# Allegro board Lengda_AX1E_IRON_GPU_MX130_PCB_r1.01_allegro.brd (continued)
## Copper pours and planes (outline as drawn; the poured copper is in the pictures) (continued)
GND on BOTTOM (solid shape): 43.49,52.23 44.48,52.23 44.58,52.14 44.58,47.16 44.44,47.03 44.44,47.02 44.37,46.95 44.37,45.12 44.3,45.05 44.3,42.58 44.29,42.58 43.28,42.58 43.26,42.6 43.26,43.36 43.61,43.71 43.61,43.72 43.8,43.91 43.8,44.47 43.7,44.57 43.41,44.57 43.28,44.7 43.26,44.72 43.26,45.03 43.36,45.13 43.4,45.13 43.53,45.26 43.53,46.34 43.46,46.41 43.21,46.41 43.19,46.44 43.19,47.06 43.36,47.23 43.36,48.42 43.16,48.62 43.16,49.13 42.92,49.37 42.47,49.37 42.08,49.76 42.08,50.24 42,50.31 41.41,50.31 41.16,50.07 41.16,49.76 41.1,49.7 40.24,49.7 40.18,49.75 40.18,52.1 40.24,52.15 42.21,52.15 42.4,52.35 43.37,52.35
GND on BOTTOM (solid shape): outline of 337 points within 31.01,32.84 38.96,52.39
GND on BOTTOM (solid shape): outline of 548 points within 7.01,3.51 76.19,97.79
GND on L2 (solid shape): outline of 35099 points within 7.01,0.41 76.19,97.79
GND on L3 (solid shape): outline of 531 points within 7.01,0.41 76.19,97.79
GND on L4 (solid shape): outline of 11258 points within 7.01,0.41 76.19,97.79
GND on L5 (solid shape): outline of 35099 points within 7.01,0.41 76.19,97.79
GND on L6 (solid shape): outline of 1050 points within 7.01,0.41 76.19,97.79
GND on L7 (solid shape): outline of 35079 points within 7.01,0.41 76.19,97.79
VDD_GPU on BOTTOM (solid shape): 66.54,64.28 66.54,63.82 66.74,63.62 66.74,62.2 66.61,62.07 65.82,62.07 65.43,61.68 62.52,61.68 62.27,61.92 62.27,64.32 62.45,64.5 66.32,64.5
VDD_GPU_AON on BOTTOM (solid shape): 65.75,60.78 66.61,60.78 66.71,60.67 66.71,60 66.36,59.64 65.15,59.64 64.9,59.39 64.9,57.22 64.19,56.51 64.19,53.9 63.7,53.42 61.91,53.42 61.84,53.5 61.84,54.22 61.29,54.77 61.29,57.13 61.62,57.46 62.1,57.46 62.7,58.06 62.7,59.67 62.43,59.94 62.43,60.84 62.6,61 65.52,61
VDD_GPU_MAIN on BOTTOM (solid shape): outline of 165 points within 55.74,53.42 61.09,58.57
+VSYS_DCIN on TOP (solid shape): outline of 100 points within 67.39,57.83 74.51,63.82
+VSYS_DCIN on TOP (solid shape): outline of 2921 points within 9.23,0.32 72.81,49.33
+VSYS_DCIN on BOTTOM (solid shape): outline of 148 points within 66.68,11.28 75.45,64.76
FB_PLLAVDD on BOTTOM (solid shape): 54.83,56.42 55.78,56.42 55.88,56.32 55.88,55.43 55.28,54.83 55.28,54.37 54.95,54.04 54.1,54.04 53.66,54.49 50.98,54.49 50.76,54.7 49.5,54.7 49.28,54.93 49.28,56.15 49.4,56.28 50.09,56.28 50.22,56.15 50.22,55.63 50.39,55.45 51.13,55.45 51.26,55.33 53.06,55.33 53.43,55.7 53.43,56.65 53.54,56.76 54.48,56.76
FB_PLLAVDD on L3 (solid shape): outline of 1169 points within 32.45,48.93 50.14,55.56
FBVDD on TOP (solid shape): 22.19,87.36 22.19,86.15 21.37,85.34 21.37,84.75 21.25,84.63 20.33,84.63 20.05,84.35 20.05,81.68 20.42,81.31 21.25,81.31 21.5,81.06 21.5,80.32 21.25,80.07 20.08,80.07 19.81,80.33 19.08,80.33 18.21,81.2 18.21,87.13 18.58,87.5 22.05,87.5
FBVDD on TOP (solid shape): 49.25,87.84 49.25,86.63 47.88,85.26 47.88,81.51 44.12,77.75 44.12,73.17 42.7,71.75 38.16,71.75 37.83,72.08 37.83,74.72 39.93,74.72 39.93,72.28 40,72.21 42.16,72.21 42.25,72.29 42.25,74.76 42.19,74.82 42.19,74.83 40.04,74.83 39.93,74.72 37.83,74.72 37.83,79.3 36.35,80.79 34.75,80.79 34.61,80.93 34.61,81.65 34.94,81.98 35.89,81.98 36.07,82.16 36.07,83.67 35.85,83.89 34.71,83.89 34.63,83.97 34.63,84.4 40.28,84.4 40.28,81.72 40.49,81.51 42.38,81.51 42.56,81.69 42.56,84.38 42.29,84.65 40.54,84.65 40.28,84.4 34.63,84.4 34.63,84.66 34.87,84.91 36.17,84.91 36.55,85.29 36.55,87.34 37.41,88.21 48.88,88.21
FBVDD on TOP (solid shape): outline of 324 points within 12.4,45.29 25.82,82.15
FBVDD on TOP (solid shape): outline of 194 points within 31.98,46.18 44.18,54.32
FBVDD on BOTTOM (solid shape): outline of 2837 points within 9.27,44.75 67.98,90.26
FBVDD on L4 (solid shape): outline of 19972 points within 12.7,44.66 65.21,87.2
GPU_PLLVDD on BOTTOM (solid shape): 60.91,61.77 60.91,59.59 60.4,59.09 58.89,59.09 58.69,59.29 58.69,60.32 58.33,60.67 57.12,60.67 56.96,60.84 56.96,61.75 57.18,61.97 60.71,61.97
GPU_PLLVDD on BOTTOM (solid shape): 40.28,36.53 40.28,34.49 39.87,34.07 38.53,34.07 38.42,34.18 38.42,35.82 38.42,36.42 38.59,36.59 40.23,36.59
NVVDD on TOP (solid shape): outline of 1458 points within 55.65,27.55 69.42,48.44
NVVDD on TOP (solid shape): outline of 1802 points within 32.95,25.88 46.74,52.42
NVVDD on BOTTOM (solid shape): 59.18,34.04 59.18,32.03 60.31,30.9 61.59,30.9 62.24,30.26 62.24,24.79 62.1,24.66 56.62,24.66 55.84,25.43 55.84,35.13 56.24,35.53 57.7,35.53
NVVDD on BOTTOM (solid shape): outline of 622 points within 35.1,24.91 46.33,51.93
NVVDD on L3 (solid shape): outline of 4621 points within 34.19,19.74 59.61,51.8
NVVDD on L4 (solid shape): outline of 4760 points within 34.3,19.75 59.55,51.67
NVVDD on L6 (solid shape): outline of 4985 points within 31.1,20.47 61.73,52.02
PEX_PLL_HVDD on BOTTOM (solid shape): 45.23,44.09 45.23,43.03 45.12,42.78 45.23,42.53 45.23,42.21 45.1,41.96 45.21,41.7 45.21,39.35 45.71,38.85 46.57,38.85 46.68,38.75 46.68,34.84 46.58,34.74 45.61,34.74 45.34,35.01 45.34,35.81 43.65,37.5 43.65,38.97 43.68,39.05 43.76,39.07 44.17,39.45 43.76,39.83 43.68,39.86 43.65,39.93 43.65,42.39 43.69,42.42 44.31,42.42 44.31,42.42 44.38,42.42 44.44,42.48 44.44,42.51 44.45,42.52 44.45,44.21 45.11,44.21
PEX_VDD on TOP (solid shape): outline of 94 points within 44.31,53.3 64.3,63.26
PEX_VDD on BOTTOM (solid shape): 59.4,49.76 59.4,46.96 58.85,46.41 55.27,46.41 54.97,46.72 54.97,47.77 55.13,47.94 56.35,47.94 56.63,48.21 56.63,49.84 56.69,49.9 59.26,49.9
PEX_VDD on BOTTOM (solid shape): outline of 376 points within 43.84,52.38 58.23,60.53
PEX_VDD on L6 (solid shape): outline of 1462 points within 44.03,48.56 62.9,60.57
PS1_NVVDD_PH1_Q on TOP (solid shape): 72.76,56.52 72.76,55.87 73.18,55.45 73.93,55.45 73.99,55.39 73.99,51.15 73.8,50.96 63.17,50.96 62.83,51.3 62.83,55.11 63.4,55.68 65.41,55.68 66.43,56.7 72.57,56.7
PS1_NVVDD_PH1_Q on BOTTOM (solid shape): 70.82,55.64 70.82,51.1 70.61,50.89 66.12,50.89 65.87,51.14 65.87,55.81 66.47,56.41 70.05,56.41
PS1_NVVDD_PH2_Q on TOP (solid shape): 74.05,26.33 74.05,22 73.51,21.46 72.54,21.46 71.53,20.44 67.72,20.44 67.46,20.69 67.46,21.46 67.19,21.73 62.69,21.73 62.45,21.98 62.45,25.48 63.4,26.43 73.95,26.43
PS1_NVVDD_PH2_Q on BOTTOM (solid shape): 70.9,25.94 70.9,21.6 70.56,21.25 65.82,21.25 64.09,22.99 64.09,26.12 64.4,26.43 70.41,26.43
PS5_1V05_SNUB on TOP (solid shape): 67.5,72.47 67.5,71.8 67.39,71.68 65.58,71.68 65.52,71.75 65.52,72.6 65.67,72.75 67.22,72.75
SP_PLLVDD on BOTTOM (solid shape): 38.4,40.83 38.4,40.04 38.55,39.9 38.55,39.71 38.49,39.65 38.43,39.55 38.41,39.42 38.43,39.29 38.45,39.26 38.52,39.16 38.63,39.08 38.74,39.05 38.83,39.05 38.85,39.05 38.98,38.92 38.99,38.92 38.99,37.2 38.53,36.74 38.52,36.74 38.27,36.48 38.27,35.82 38.26,35.81 37.51,35.81 37.43,35.89 37.43,37.09 37.59,37.25 37.59,39.21 37.53,39.27 37.53,39.34 37.45,39.64 37.17,39.78 37.14,39.78 36.91,40.01 36.91,40.4 36.97,40.46 37.29,40.46 37.32,40.49 37.4,40.49 37.78,40.87 38.36,40.87
N37829238 on TOP (solid shape): outline of 2240 points within 44.33,43.57 51.94,58.18
N37829238 on BOTTOM (solid shape): outline of 103 points within 44.46,44.4 58.61,53.42
N37829238 on L6 (solid shape): outline of 669 points within 44.06,44.36 56.11,52.13
N37848751 on TOP (solid shape): 33.6,45.81 33.6,45.73 34.05,45.28 34.05,43.59 33.89,43.43 33.56,43.43 33.29,43.71 32.94,43.71 32.85,43.8 32.85,44.58 33.31,45.04 33.31,45.19 33.31,45.19 33.24,45.36 33.2,45.44 33.05,45.55 33.04,45.56 33.04,45.7 33.27,45.93 33.49,45.93
N37848802 on TOP (solid shape): 33.59,43.21 33.97,43.21 34.06,43.16 34.07,41.82 33.94,41.69 33.67,41.69 33.51,41.85 33.15,41.85 32.87,42.14 32.87,43.45 32.91,43.49 33.15,43.49 33.16,43.49 33.25,43.49
N37848802 on BOTTOM (solid shape): 33.98,42.09 33.98,40.97 33.31,40.3 33.31,40.04 33.26,40 32.74,40 32.67,40.07 32.67,41.52 32.55,41.63 32.55,41.63 32.55,42.11 32.7,42.26 33.81,42.26
N37866054 on TOP (solid shape): 17.33,59.51 17.33,57.36 17.29,57.35 16.92,56.86 17.29,56.38 17.33,56.37 17.33,51.05 16.6,50.32 12.32,50.32 12.2,50.44 12.2,59.95 12.52,60.27 16.57,60.27
N37870106 on TOP (solid shape): 68.95,71.44 68.95,68 66.18,65.23 61.43,65.23 61.41,65.25 61.37,65.29 61.32,65.33 61.27,65.35 61.22,65.37 61.16,65.38 61.11,65.38 61.05,65.38 61,65.36 60.95,65.34 60.9,65.31 60.86,65.27 60.82,65.23 60.76,65.23 60.16,65.83 60.16,66.12 65.62,66.12 65.62,66.07 65.64,66.01 65.66,65.96 65.68,65.91 65.72,65.87 65.76,65.83 65.8,65.8 65.85,65.77 65.9,65.76 65.96,65.75 66.01,65.74 66.07,65.75 66.12,65.76 66.17,65.78 66.22,65.81 66.26,65.85 66.3,65.89 66.33,65.94 66.35,65.99 66.37,66.04 66.38,66.09 66.38,66.15 66.37,66.2 66.35,66.26 66.33,66.31 66.3,66.35 66.26,66.39 66.22,66.43 66.17,66.46 66.12,66.48 66.07,66.49 66.01,66.5 65.96,66.5 65.9,66.49 65.85,66.47 65.8,66.45 65.76,66.41 65.72,66.37 65.68,66.33 65.66,66.28 65.64,66.23 65.62,66.18 65.62,66.12 60.16,66.12 60.16,69.22 60.39,69.45 64.9,69.45 66.96,71.51 68.88,71.51
N377218676 on BOTTOM (solid shape): 54.53,48.03 54.53,46.74 49.32,46.74 49.32,47.59 49.5,47.77 53.04,47.77 53.35,48.08 54.48,48.08
N377220203 on TOP (solid shape): 72.63,88.84 72.63,86.58 72.42,86.37 71.04,86.37 70.28,85.6 70.28,84.73 70.05,84.5 66.88,84.5 66.74,84.64 66.74,86.99 66.85,87.1 66.85,87.11 69.62,87.11 69.91,87.41 69.91,89.26 69.99,89.34 72.14,89.34

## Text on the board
Ref Des/Silkscreen Bottom: BA | BOT V1.01 | 5000-0007-3821 | 2018.0105.1700 | IRON_GPU_MX130_PCB | BB | BOTTOM | REF
Ref Des/Silkscreen Top: TOP V1.01 | 5000-0007-3821 | 2018.0105.1700 | IRON_GPU_MX130_PCB | TA | REF | TOP
User.26: FIGURE | SIZE | 9.84 | 11.02 | 15.75 | 90.55 | 133.86 | 78.74 | DRILL CHART: TOP to BOTTOM | ALL UNITS ARE IN MILS | TOLERANCE | +0.0/-0.0 | +2.95/-2.95 | PLATED | NON-PLATED | QTY | 1320 | 41 | 227 | 8 | 3 | 4
